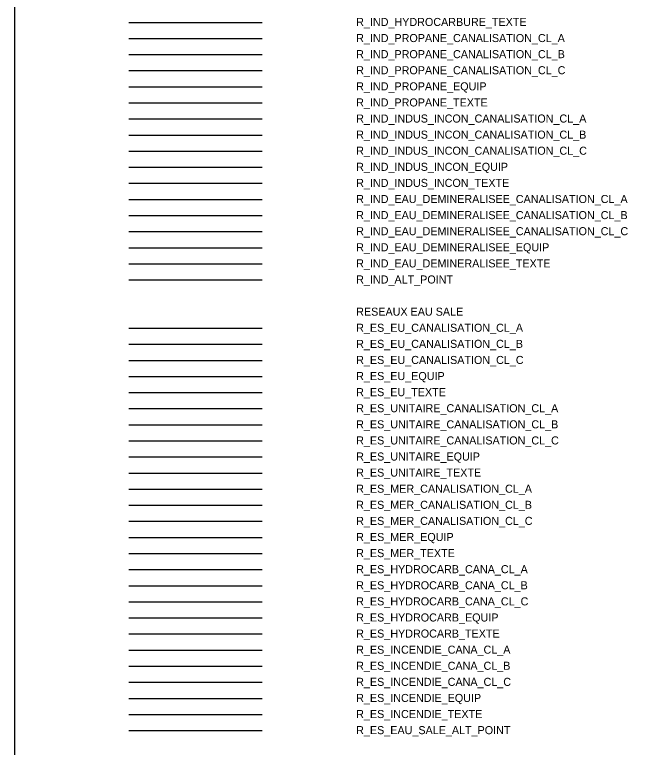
# Model space of a CAD drawing. Extents: x -60 to 214, y -380 to -21.
# Drawn here: x 33.07 to 72.77, y -201.47 to -155.95 of the extents above; entities that cross this region are included whole.
import ezdxf

# ---------------------------------------------------------------- set-up
doc = ezdxf.new("R2010")
doc.units = 0
for name, color, linetype in [('Default', 7, 'Continuous'), ('DH_TEXTE', 7, 'Continuous'), ('R_ES_EAU_SALE_ALT_POINT', 7, 'Continuous'), ('R_ES_EU_CANALISATION_CL_A', 7, 'Continuous'), ('R_ES_EU_CANALISATION_CL_B', 7, 'Continuous'), ('R_ES_EU_CANALISATION_CL_C', 7, 'Continuous'), ('R_ES_EU_EQUIP', 7, 'Continuous'), ('R_ES_EU_TEXTE', 7, 'Continuous'), ('R_ES_HYDROCARB_CANA_CL_A', 7, 'Continuous'), ('R_ES_HYDROCARB_CANA_CL_B', 7, 'Continuous'), ('R_ES_HYDROCARB_CANA_CL_C', 7, 'Continuous'), ('R_ES_HYDROCARB_EQUIP', 7, 'Continuous'), ('R_ES_HYDROCARB_TEXTE', 7, 'Continuous'), ('R_ES_INCENDIE_CANA_CL_A', 7, 'Continuous'), ('R_ES_INCENDIE_CANA_CL_B', 7, 'Continuous'), ('R_ES_INCENDIE_CANA_CL_C', 7, 'Continuous'), ('R_ES_INCENDIE_EQUIP', 7, 'Continuous'), ('R_ES_INCENDIE_TEXTE', 7, 'Continuous'), ('R_ES_MER_CANALISATION_CL_A', 7, 'Continuous'), ('R_ES_MER_CANALISATION_CL_B', 7, 'Continuous'), ('R_ES_MER_CANALISATION_CL_C', 7, 'Continuous'), ('R_ES_MER_EQUIP', 7, 'Continuous'), ('R_ES_MER_TEXTE', 7, 'Continuous'), ('R_ES_UNITAIRE_CANALISATION_CL_A', 7, 'Continuous'), ('R_ES_UNITAIRE_CANALISATION_CL_B', 7, 'Continuous'), ('R_ES_UNITAIRE_CANALISATION_CL_C', 7, 'Continuous'), ('R_ES_UNITAIRE_EQUIP', 7, 'Continuous'), ('R_ES_UNITAIRE_TEXTE', 7, 'Continuous'), ('R_IND_ALT_POINT', 7, 'Continuous'), ('R_IND_EAU_DEMINERALISEE_CANALISATION_CL_A', 7, 'Continuous'), ('R_IND_EAU_DEMINERALISEE_CANALISATION_CL_B', 7, 'Continuous'), ('R_IND_EAU_DEMINERALISEE_CANALISATION_CL_C', 7, 'Continuous'), ('R_IND_EAU_DEMINERALISEE_EQUIP', 7, 'Continuous'), ('R_IND_EAU_DEMINERALISEE_TEXTE', 7, 'Continuous'), ('R_IND_HYDROCARBURE_TEXTE', 7, 'Continuous'), ('R_IND_INDUS_INCON_CANALISATION_CL_A', 7, 'Continuous'), ('R_IND_INDUS_INCON_CANALISATION_CL_B', 7, 'Continuous'), ('R_IND_INDUS_INCON_CANALISATION_CL_C', 7, 'Continuous'), ('R_IND_INDUS_INCON_EQUIP', 7, 'Continuous'), ('R_IND_INDUS_INCON_TEXTE', 7, 'Continuous'), ('R_IND_PROPANE_CANALISATION_CL_A', 7, 'Continuous'), ('R_IND_PROPANE_CANALISATION_CL_B', 7, 'Continuous'), ('R_IND_PROPANE_CANALISATION_CL_C', 7, 'Continuous'), ('R_IND_PROPANE_EQUIP', 7, 'Continuous'), ('R_IND_PROPANE_TEXTE', 7, 'Continuous')]:
    doc.layers.add(name, color=color, linetype=linetype)

msp = doc.modelspace()

# ---------------------------------------------------------------- linework, layer by layer
at = {"layer": 'Default'}
msp.add_lwpolyline([(114.838, -25.727), (33.073, -25.727), (33.073, -380.216), (114.838, -380.216)], close=True, dxfattribs=at)
at = {"layer": 'R_ES_EAU_SALE_ALT_POINT'}
msp.add_line((40.178, -200.429), (48.457, -200.429), dxfattribs=at)
at = {"layer": 'R_ES_EU_CANALISATION_CL_A'}
msp.add_line((40.178, -175.429), (48.457, -175.429), dxfattribs=at)
at = {"layer": 'R_ES_EU_CANALISATION_CL_B'}
msp.add_line((40.178, -176.429), (48.457, -176.429), dxfattribs=at)
at = {"layer": 'R_ES_EU_CANALISATION_CL_C'}
msp.add_line((40.178, -177.429), (48.457, -177.429), dxfattribs=at)
at = {"layer": 'R_ES_EU_EQUIP'}
msp.add_line((40.178, -178.429), (48.457, -178.429), dxfattribs=at)
at = {"layer": 'R_ES_EU_TEXTE'}
msp.add_line((40.178, -179.429), (48.457, -179.429), dxfattribs=at)
at = {"layer": 'R_ES_HYDROCARB_CANA_CL_A'}
msp.add_line((40.178, -190.429), (48.457, -190.429), dxfattribs=at)
at = {"layer": 'R_ES_HYDROCARB_CANA_CL_B'}
msp.add_line((40.178, -191.429), (48.457, -191.429), dxfattribs=at)
at = {"layer": 'R_ES_HYDROCARB_CANA_CL_C'}
msp.add_line((40.178, -192.429), (48.457, -192.429), dxfattribs=at)
at = {"layer": 'R_ES_HYDROCARB_EQUIP'}
msp.add_line((40.178, -193.429), (48.457, -193.429), dxfattribs=at)
at = {"layer": 'R_ES_HYDROCARB_TEXTE'}
msp.add_line((40.178, -194.429), (48.457, -194.429), dxfattribs=at)
at = {"layer": 'R_ES_INCENDIE_CANA_CL_A'}
msp.add_line((40.178, -195.429), (48.457, -195.429), dxfattribs=at)
at = {"layer": 'R_ES_INCENDIE_CANA_CL_B'}
msp.add_line((40.178, -196.429), (48.457, -196.429), dxfattribs=at)
at = {"layer": 'R_ES_INCENDIE_CANA_CL_C'}
msp.add_line((40.178, -197.429), (48.457, -197.429), dxfattribs=at)
at = {"layer": 'R_ES_INCENDIE_EQUIP'}
msp.add_line((40.178, -198.429), (48.457, -198.429), dxfattribs=at)
at = {"layer": 'R_ES_INCENDIE_TEXTE'}
msp.add_line((40.178, -199.429), (48.457, -199.429), dxfattribs=at)
at = {"layer": 'R_ES_MER_CANALISATION_CL_A'}
msp.add_line((40.178, -185.429), (48.457, -185.429), dxfattribs=at)
at = {"layer": 'R_ES_MER_CANALISATION_CL_B'}
msp.add_line((40.178, -186.429), (48.457, -186.429), dxfattribs=at)
at = {"layer": 'R_ES_MER_CANALISATION_CL_C'}
msp.add_line((40.178, -187.429), (48.457, -187.429), dxfattribs=at)
at = {"layer": 'R_ES_MER_EQUIP'}
msp.add_line((40.178, -188.429), (48.457, -188.429), dxfattribs=at)
at = {"layer": 'R_ES_MER_TEXTE'}
msp.add_line((40.178, -189.429), (48.457, -189.429), dxfattribs=at)
at = {"layer": 'R_ES_UNITAIRE_CANALISATION_CL_A'}
msp.add_line((40.178, -180.429), (48.457, -180.429), dxfattribs=at)
at = {"layer": 'R_ES_UNITAIRE_CANALISATION_CL_B'}
msp.add_line((40.178, -181.429), (48.457, -181.429), dxfattribs=at)
at = {"layer": 'R_ES_UNITAIRE_CANALISATION_CL_C'}
msp.add_line((40.178, -182.429), (48.457, -182.429), dxfattribs=at)
at = {"layer": 'R_ES_UNITAIRE_EQUIP'}
msp.add_line((40.178, -183.429), (48.457, -183.429), dxfattribs=at)
at = {"layer": 'R_ES_UNITAIRE_TEXTE'}
msp.add_line((40.178, -184.429), (48.457, -184.429), dxfattribs=at)
at = {"layer": 'R_IND_ALT_POINT'}
msp.add_line((40.178, -172.429), (48.457, -172.429), dxfattribs=at)
at = {"layer": 'R_IND_EAU_DEMINERALISEE_CANALISATION_CL_A'}
msp.add_line((40.178, -167.429), (48.457, -167.429), dxfattribs=at)
at = {"layer": 'R_IND_EAU_DEMINERALISEE_CANALISATION_CL_B'}
msp.add_line((40.178, -168.429), (48.457, -168.429), dxfattribs=at)
at = {"layer": 'R_IND_EAU_DEMINERALISEE_CANALISATION_CL_C'}
msp.add_line((40.178, -169.429), (48.457, -169.429), dxfattribs=at)
at = {"layer": 'R_IND_EAU_DEMINERALISEE_EQUIP'}
msp.add_line((40.178, -170.429), (48.457, -170.429), dxfattribs=at)
at = {"layer": 'R_IND_EAU_DEMINERALISEE_TEXTE'}
msp.add_line((40.178, -171.429), (48.457, -171.429), dxfattribs=at)
at = {"layer": 'R_IND_HYDROCARBURE_TEXTE'}
msp.add_line((40.178, -156.429), (48.457, -156.429), dxfattribs=at)
at = {"layer": 'R_IND_INDUS_INCON_CANALISATION_CL_A'}
msp.add_line((40.178, -162.429), (48.457, -162.429), dxfattribs=at)
at = {"layer": 'R_IND_INDUS_INCON_CANALISATION_CL_B'}
msp.add_line((40.178, -163.429), (48.457, -163.429), dxfattribs=at)
at = {"layer": 'R_IND_INDUS_INCON_CANALISATION_CL_C'}
msp.add_line((40.178, -164.429), (48.457, -164.429), dxfattribs=at)
at = {"layer": 'R_IND_INDUS_INCON_EQUIP'}
msp.add_line((40.178, -165.429), (48.457, -165.429), dxfattribs=at)
at = {"layer": 'R_IND_INDUS_INCON_TEXTE'}
msp.add_line((40.178, -166.429), (48.457, -166.429), dxfattribs=at)
at = {"layer": 'R_IND_PROPANE_CANALISATION_CL_A'}
msp.add_line((40.178, -157.429), (48.457, -157.429), dxfattribs=at)
at = {"layer": 'R_IND_PROPANE_CANALISATION_CL_B'}
msp.add_line((40.178, -158.429), (48.457, -158.429), dxfattribs=at)
at = {"layer": 'R_IND_PROPANE_CANALISATION_CL_C'}
msp.add_line((40.178, -159.429), (48.457, -159.429), dxfattribs=at)
at = {"layer": 'R_IND_PROPANE_EQUIP'}
msp.add_line((40.178, -160.429), (48.457, -160.429), dxfattribs=at)
at = {"layer": 'R_IND_PROPANE_TEXTE'}
msp.add_line((40.178, -161.429), (48.457, -161.429), dxfattribs=at)

# ---------------------------------------------------------------- texts
at = {"layer": 'DH_TEXTE'}
msp.add_text('RESEAUX EAU SALE', height=0.5, dxfattribs=at).set_placement((54.301, -174.655))
at = {"layer": 'R_ES_EAU_SALE_ALT_POINT'}
msp.add_text('R_ES_EAU_SALE_ALT_POINT  ', height=0.5, dxfattribs=at).set_placement((54.301, -200.655))
at = {"layer": 'R_ES_EU_CANALISATION_CL_A'}
msp.add_text('R_ES_EU_CANALISATION_CL_A ', height=0.5, dxfattribs=at).set_placement((54.301, -175.655))
at = {"layer": 'R_ES_EU_CANALISATION_CL_B'}
msp.add_text('R_ES_EU_CANALISATION_CL_B ', height=0.5, dxfattribs=at).set_placement((54.301, -176.655))
at = {"layer": 'R_ES_EU_CANALISATION_CL_C'}
msp.add_text('R_ES_EU_CANALISATION_CL_C ', height=0.5, dxfattribs=at).set_placement((54.301, -177.655))
at = {"layer": 'R_ES_EU_EQUIP'}
msp.add_text('R_ES_EU_EQUIP ', height=0.5, dxfattribs=at).set_placement((54.301, -178.655))
at = {"layer": 'R_ES_EU_TEXTE'}
msp.add_text('R_ES_EU_TEXTE ', height=0.5, dxfattribs=at).set_placement((54.301, -179.655))
at = {"layer": 'R_ES_HYDROCARB_CANA_CL_A'}
msp.add_text('R_ES_HYDROCARB_CANA_CL_A ', height=0.5, dxfattribs=at).set_placement((54.301, -190.655))
at = {"layer": 'R_ES_HYDROCARB_CANA_CL_B'}
msp.add_text('R_ES_HYDROCARB_CANA_CL_B ', height=0.5, dxfattribs=at).set_placement((54.301, -191.655))
at = {"layer": 'R_ES_HYDROCARB_CANA_CL_C'}
msp.add_text('R_ES_HYDROCARB_CANA_CL_C ', height=0.5, dxfattribs=at).set_placement((54.301, -192.655))
at = {"layer": 'R_ES_HYDROCARB_EQUIP'}
msp.add_text('R_ES_HYDROCARB_EQUIP ', height=0.5, dxfattribs=at).set_placement((54.301, -193.655))
at = {"layer": 'R_ES_HYDROCARB_TEXTE'}
msp.add_text('R_ES_HYDROCARB_TEXTE ', height=0.5, dxfattribs=at).set_placement((54.301, -194.655))
at = {"layer": 'R_ES_INCENDIE_CANA_CL_A'}
msp.add_text('R_ES_INCENDIE_CANA_CL_A ', height=0.5, dxfattribs=at).set_placement((54.301, -195.655))
at = {"layer": 'R_ES_INCENDIE_CANA_CL_B'}
msp.add_text('R_ES_INCENDIE_CANA_CL_B ', height=0.5, dxfattribs=at).set_placement((54.301, -196.655))
at = {"layer": 'R_ES_INCENDIE_CANA_CL_C'}
msp.add_text('R_ES_INCENDIE_CANA_CL_C ', height=0.5, dxfattribs=at).set_placement((54.301, -197.655))
at = {"layer": 'R_ES_INCENDIE_EQUIP'}
msp.add_text('R_ES_INCENDIE_EQUIP ', height=0.5, dxfattribs=at).set_placement((54.301, -198.655))
at = {"layer": 'R_ES_INCENDIE_TEXTE'}
msp.add_text('R_ES_INCENDIE_TEXTE ', height=0.5, dxfattribs=at).set_placement((54.301, -199.655))
at = {"layer": 'R_ES_MER_CANALISATION_CL_A'}
msp.add_text('R_ES_MER_CANALISATION_CL_A ', height=0.5, dxfattribs=at).set_placement((54.301, -185.655))
at = {"layer": 'R_ES_MER_CANALISATION_CL_B'}
msp.add_text('R_ES_MER_CANALISATION_CL_B ', height=0.5, dxfattribs=at).set_placement((54.301, -186.655))
at = {"layer": 'R_ES_MER_CANALISATION_CL_C'}
msp.add_text('R_ES_MER_CANALISATION_CL_C ', height=0.5, dxfattribs=at).set_placement((54.301, -187.655))
at = {"layer": 'R_ES_MER_EQUIP'}
msp.add_text('R_ES_MER_EQUIP ', height=0.5, dxfattribs=at).set_placement((54.301, -188.655))
at = {"layer": 'R_ES_MER_TEXTE'}
msp.add_text('R_ES_MER_TEXTE ', height=0.5, dxfattribs=at).set_placement((54.301, -189.655))
at = {"layer": 'R_ES_UNITAIRE_CANALISATION_CL_A'}
msp.add_text('R_ES_UNITAIRE_CANALISATION_CL_A ', height=0.5, dxfattribs=at).set_placement((54.301, -180.655))
at = {"layer": 'R_ES_UNITAIRE_CANALISATION_CL_B'}
msp.add_text('R_ES_UNITAIRE_CANALISATION_CL_B ', height=0.5, dxfattribs=at).set_placement((54.301, -181.655))
at = {"layer": 'R_ES_UNITAIRE_CANALISATION_CL_C'}
msp.add_text('R_ES_UNITAIRE_CANALISATION_CL_C ', height=0.5, dxfattribs=at).set_placement((54.301, -182.655))
at = {"layer": 'R_ES_UNITAIRE_EQUIP'}
msp.add_text('R_ES_UNITAIRE_EQUIP ', height=0.5, dxfattribs=at).set_placement((54.301, -183.655))
at = {"layer": 'R_ES_UNITAIRE_TEXTE'}
msp.add_text('R_ES_UNITAIRE_TEXTE ', height=0.5, dxfattribs=at).set_placement((54.301, -184.655))
at = {"layer": 'R_IND_ALT_POINT'}
msp.add_text('R_IND_ALT_POINT  ', height=0.5, dxfattribs=at).set_placement((54.301, -172.655))
at = {"layer": 'R_IND_EAU_DEMINERALISEE_CANALISATION_CL_A'}
msp.add_text('R_IND_EAU_DEMINERALISEE_CANALISATION_CL_A ', height=0.5, dxfattribs=at).set_placement((54.301, -167.655))
at = {"layer": 'R_IND_EAU_DEMINERALISEE_CANALISATION_CL_B'}
msp.add_text('R_IND_EAU_DEMINERALISEE_CANALISATION_CL_B ', height=0.5, dxfattribs=at).set_placement((54.301, -168.655))
at = {"layer": 'R_IND_EAU_DEMINERALISEE_CANALISATION_CL_C'}
msp.add_text('R_IND_EAU_DEMINERALISEE_CANALISATION_CL_C ', height=0.5, dxfattribs=at).set_placement((54.301, -169.655))
at = {"layer": 'R_IND_EAU_DEMINERALISEE_EQUIP'}
msp.add_text('R_IND_EAU_DEMINERALISEE_EQUIP ', height=0.5, dxfattribs=at).set_placement((54.301, -170.655))
at = {"layer": 'R_IND_EAU_DEMINERALISEE_TEXTE'}
msp.add_text('R_IND_EAU_DEMINERALISEE_TEXTE ', height=0.5, dxfattribs=at).set_placement((54.301, -171.655))
at = {"layer": 'R_IND_HYDROCARBURE_TEXTE'}
msp.add_text('R_IND_HYDROCARBURE_TEXTE ', height=0.5, dxfattribs=at).set_placement((54.301, -156.655))
at = {"layer": 'R_IND_INDUS_INCON_CANALISATION_CL_A'}
msp.add_text('R_IND_INDUS_INCON_CANALISATION_CL_A ', height=0.5, dxfattribs=at).set_placement((54.301, -162.655))
at = {"layer": 'R_IND_INDUS_INCON_CANALISATION_CL_B'}
msp.add_text('R_IND_INDUS_INCON_CANALISATION_CL_B ', height=0.5, dxfattribs=at).set_placement((54.301, -163.655))
at = {"layer": 'R_IND_INDUS_INCON_CANALISATION_CL_C'}
msp.add_text('R_IND_INDUS_INCON_CANALISATION_CL_C ', height=0.5, dxfattribs=at).set_placement((54.301, -164.655))
at = {"layer": 'R_IND_INDUS_INCON_EQUIP'}
msp.add_text('R_IND_INDUS_INCON_EQUIP ', height=0.5, dxfattribs=at).set_placement((54.301, -165.655))
at = {"layer": 'R_IND_INDUS_INCON_TEXTE'}
msp.add_text('R_IND_INDUS_INCON_TEXTE ', height=0.5, dxfattribs=at).set_placement((54.301, -166.655))
at = {"layer": 'R_IND_PROPANE_CANALISATION_CL_A'}
msp.add_text('R_IND_PROPANE_CANALISATION_CL_A ', height=0.5, dxfattribs=at).set_placement((54.301, -157.655))
at = {"layer": 'R_IND_PROPANE_CANALISATION_CL_B'}
msp.add_text('R_IND_PROPANE_CANALISATION_CL_B ', height=0.5, dxfattribs=at).set_placement((54.301, -158.655))
at = {"layer": 'R_IND_PROPANE_CANALISATION_CL_C'}
msp.add_text('R_IND_PROPANE_CANALISATION_CL_C ', height=0.5, dxfattribs=at).set_placement((54.301, -159.655))
at = {"layer": 'R_IND_PROPANE_EQUIP'}
msp.add_text('R_IND_PROPANE_EQUIP ', height=0.5, dxfattribs=at).set_placement((54.301, -160.655))
at = {"layer": 'R_IND_PROPANE_TEXTE'}
msp.add_text('R_IND_PROPANE_TEXTE ', height=0.5, dxfattribs=at).set_placement((54.301, -161.655))

doc.saveas('drawing.dxf')
